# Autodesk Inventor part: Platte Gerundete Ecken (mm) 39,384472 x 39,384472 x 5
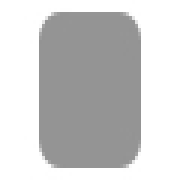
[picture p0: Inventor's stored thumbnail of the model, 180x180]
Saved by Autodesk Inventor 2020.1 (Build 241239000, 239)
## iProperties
Created: 2019-01
Part Number: Platte Gerundete Ecken (mm) 39,384472 x 39,384472 x 5
Material: Stahl, weich
Document SubType Name: Modeling
Designer: lutzd
Language: de-DE
Size Designation: 5 x 39,384472 x 39,384472
Categories: <MemberInstance><Categories><Category DisplayName="Sonstige Bauteile" InternalName="5aa15e00-363f-49f2-933f-16f664388e3f" Mnemonic="OTHER"><Category DisplayName
Mass: 60.0398 g
Surface Area: 38.0412 cm^2
Volume: 7.64838 cm^3
Density: 7.85 g/cm^3
Appearance: Halbpoliert
IsCustomPart: 1
Dimensions: 39,4x39,4x5 mm
Mass: 0,06 kg
Author: lutzd
Revision Number: -
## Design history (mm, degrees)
sketch "Sketch1"
  geometry: L1 (0, 20.175)-(0, -21.446); L2 (-20.203, 0)-(20.169, 0); L3 (-19.692, 19.692)-(19.692, 19.692); L4 (19.692, 19.692)-(19.692, -19.692); L5 (19.692, -19.692)-(-19.692, -19.692); L6 (-19.692, -19.692)-(-19.692, 19.692); 1 further point
  constraints: 12 end point, 2 horizontal, 2 parallel, 2 point on line, 1 perpendicular, 1 vertical
  dimensions: "d0" = 39.38447 distance between parallel lines of L5 L3 (= height); "d1" = 19.69224 distance between parallel lines of L2 L3 (= 0.5 x height); "d2" = 39.38447 distance between parallel lines of L6 L4 (= width); "d3" = 19.69224 distance between parallel lines of L6 L1 (= 0.5 x width)
extrude "Extrusion1" new body sketch "Sketch1" distance "d4" = 5 (= thickness); taper "d5" = 0 deg
fillet "Fillet1" dims "d6" = 5 (= fillet), "d7" = 0, "fillet" = 5 [user parameter; used in 1 equation term]
chamfer "Chamfer1" distance "d8" = 0 (computed from chamfer); stored, may be unused: second distance "d9" = 2, angle "d10" = 45 deg; dims "d11" = 0, "chamfer" = 0 [user parameter; used in 1 equation term]
body "Solid1"
other parameters: "thickness" = 5 [user parameter; used in 1 equation term], "width" = 39.38447 [user parameter; used in 2 equation terms], "height" = 39.38447 [user parameter; used in 2 equation terms]
